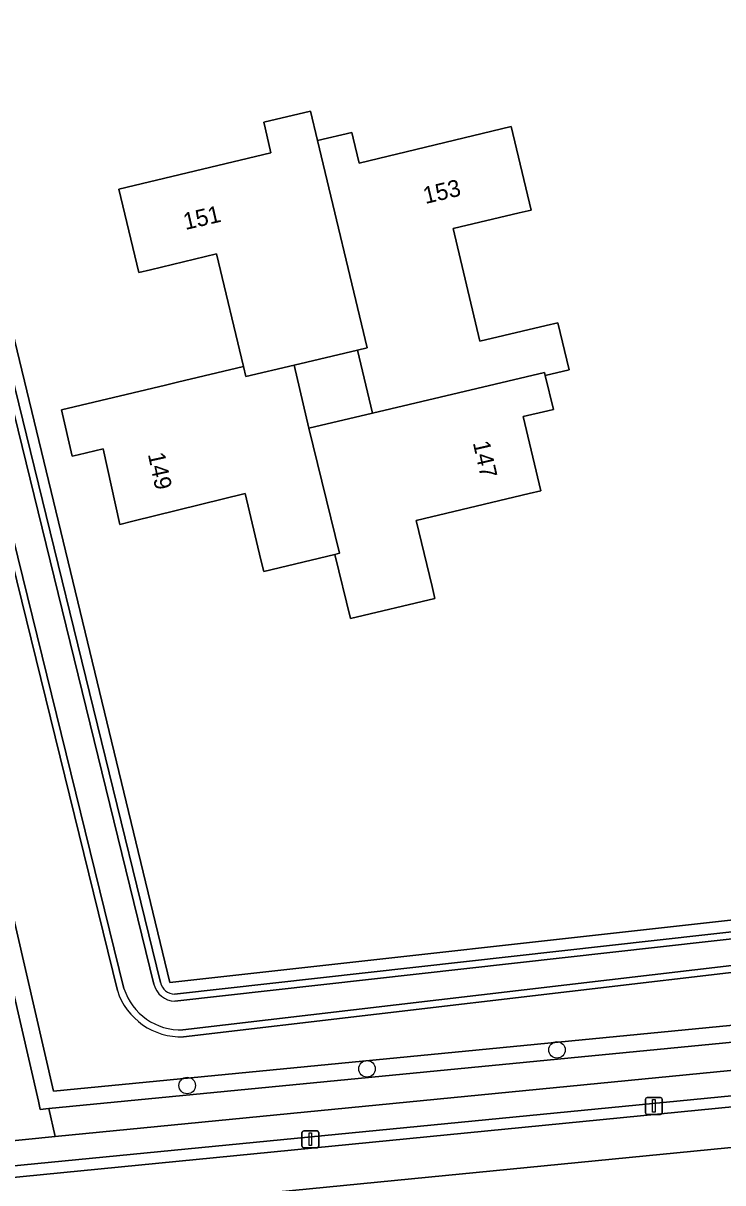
# Model space of a CAD drawing. Extents: x 156661 to 157576, y 383570 to 384425.
# Drawn here: x 156873.3 to 156914.8, y 383918.1 to 383986.9 of the extents above; entities that cross this region are included whole.
import ezdxf

# ---------------------------------------------------------------- set-up
doc = ezdxf.new("R2010")
doc.units = 0
for name, color, linetype in [('IMGEO_Berm_groen', 7, 'Continuous'), ('IMGEO_Boom', 7, 'Continuous'), ('IMGEO_Erf', 7, 'Continuous'), ('IMGEO_Groenvoorziening', 7, 'Continuous'), ('IMGEO_Haag', 7, 'Continuous'), ('IMGEO_Hek', 7, 'Continuous'), ('IMGEO_Lichtmast', 7, 'Continuous'), ('IMGEO_Oever', 7, 'Continuous'), ('IMGEO_Pand', 7, 'Continuous'), ('IMGEO_Pand_nummerreeks', 7, 'Continuous'), ('IMGEO_Parkeervlak_open', 7, 'Continuous'), ('IMGEO_Rijbaan_lokaal_open', 7, 'Continuous'), ('IMGEO_Voetpad_open', 7, 'Continuous'), ('IMGEO_Waterloop', 7, 'Continuous')]:
    doc.layers.add(name, color=color, linetype=linetype)

msp = doc.modelspace()

# ---------------------------------------------------------------- linework, layer by layer
at = {"layer": 'IMGEO_Berm_groen'}
msp.add_lwpolyline([(156853.805, 383916.581), (156939.653, 383925.02), (156939.883, 383922.625), (156942.261, 383922.858), (156942.029, 383925.893), (156868.496, 383918.711), (156853.282, 383917.324)], dxfattribs=at)
at = {"layer": 'IMGEO_Boom'}
for centre in [(156904.96, 383926.003), (156893.698, 383924.879), (156883.044, 383923.891)]:
    msp.add_circle(centre, 0.489, dxfattribs=at)
at = {"layer": 'IMGEO_Erf'}
msp.add_lwpolyline([(156971.911, 384032.865), (156863.465, 384006.689), (156882.007, 383929.988), (156953.099, 383937.896), (156953.011, 383938.269), (156952.494, 383938.147), (156951.881, 383940.49), (156952.407, 383940.603), (156956.295, 383941.53), (156956.425, 383941.002), (156956.745, 383941.083), (156956.615, 383941.611), (156956.564, 383941.597), (156954.882, 383948.869), (156959.573, 383949.776), (156961.258, 383942.72)], dxfattribs=at)
for points in [[(156904.752, 383963.959), (156904.41, 383963.885), (156902.961, 383963.546), (156904, 383959.146), (156903.304, 383958.979), (156896.605, 383957.372), (156897.554, 383953.467), (156897.725, 383952.763), (156892.723, 383951.572), (156891.794, 383955.374), (156887.581, 383954.357), (156887.415, 383955.055), (156886.481, 383958.979), (156879.819, 383957.338), (156879.053, 383957.149), (156878.061, 383961.622), (156876.583, 383961.277), (156876.237, 383961.196), (156875.591, 383963.935), (156881.763, 383965.402), (156882.477, 383965.573), (156886.373, 383966.505), (156884.791, 383973.185), (156880.877, 383972.245), (156880.173, 383972.085), (156878.991, 383977.02), (156888.003, 383979.182), (156887.664, 383980.648), (156887.586, 383980.987), (156890.346, 383981.649), (156890.766, 383979.898), (156892.794, 383980.386), (156892.877, 383980.046), (156893.235, 383978.562), (156902.252, 383980.728), (156903.427, 383975.777), (156902.718, 383975.608), (156898.809, 383974.679), (156900.384, 383968.006), (156904.318, 383968.932), (156905.001, 383969.095), (156905.672, 383966.301), (156904.267, 383965.968)], [(156894.022, 383963.749), (156893.142, 383967.479), (156889.376, 383966.59), (156890.256, 383962.861)]]:
    msp.add_lwpolyline(points, close=True, dxfattribs=at)
at = {"layer": 'IMGEO_Groenvoorziening'}
for points in [[(156971.825, 384035.574), (156971.462, 384036.848), (156855.447, 384008.779), (156857.538, 383999.895), (156875.116, 383923.557), (156954.665, 383931.279), (156953.099, 383937.896)], [(156953.099, 383937.896), (156882.007, 383929.988), (156863.465, 384006.689), (156971.911, 384032.865), (156984.848, 383993.384), (157001.305, 383943.16), (156963.71, 383939.037), (156964.423, 383936.119), (156965.671, 383936.392)], [(156862.766, 384006.287), (156881.463, 383929.99)], [(156878.907, 383929.526), (156860.158, 384005.773)], [(156882.291, 383929.295), (156950.98, 383936.984)], [(156951.446, 383934.836), (156882.827, 383926.782)]]:
    msp.add_lwpolyline(points, dxfattribs=at)
for points in [[(156954.897, 383930.297), (156954.665, 383931.279), (156875.116, 383923.557), (156857.538, 383999.895), (156855.447, 384008.779), (156854.961, 384008.661), (156854.475, 384008.544), (156856.565, 383999.666), (156874.225, 383922.969), (156874.338, 383922.477), (156874.835, 383922.525)], [(156874.835, 383922.525), (156874.338, 383922.477), (156874.225, 383922.969), (156856.565, 383999.666), (156854.475, 384008.544), (156851.846, 384007.908), (156849.631, 384007.372), (156870.13, 383920.364), (156875.218, 383920.862)], [(156875.218, 383920.862), (156955.275, 383928.7), (156954.897, 383930.297), (156874.835, 383922.525)]]:
    msp.add_lwpolyline(points, close=True, dxfattribs=at)
for centre, radius, start, end in [((156882.353, 383930.209), 0.916, 193.84782, 266.13387), ((156882.66, 383930.715), 3.937, 197.58244, 272.43352)]:
    msp.add_arc(centre, radius, start, end, dxfattribs=at)
at = {"layer": 'IMGEO_Haag'}
msp.add_lwpolyline([(156857.538, 383999.895), (156855.447, 384008.779), (156854.961, 384008.661), (156854.475, 384008.544), (156856.565, 383999.666), (156874.225, 383922.969), (156874.338, 383922.477), (156874.835, 383922.525), (156954.897, 383930.297), (156954.665, 383931.279), (156875.116, 383923.557)], close=True, dxfattribs=at)
at = {"layer": 'IMGEO_Hek'}
msp.add_lwpolyline([(156953.099, 383937.896), (156882.007, 383929.988), (156863.465, 384006.689), (156971.911, 384032.865), (156984.848, 383993.384), (157001.305, 383943.16)], dxfattribs=at)
at = {"layer": 'IMGEO_Lichtmast'}
for p, q in [((156910.205, 383922.277), (156910.205, 383923.077)), ((156910.205, 383923.077), (156910.205, 383922.277)), ((156910.305, 383923.177), (156911.095, 383923.177)), ((156911.095, 383923.177), (156910.305, 383923.177)), ((156911.195, 383923.077), (156911.195, 383922.277)), ((156911.195, 383922.277), (156911.195, 383923.077)), ((156911.095, 383922.177), (156910.305, 383922.177)), ((156910.305, 383922.177), (156911.095, 383922.177)), ((156889.848, 383920.302), (156889.848, 383921.102)), ((156889.848, 383921.102), (156889.848, 383920.302)), ((156889.948, 383921.202), (156890.738, 383921.202)), ((156890.738, 383921.202), (156889.948, 383921.202)), ((156890.838, 383921.102), (156890.838, 383920.302)), ((156890.838, 383920.302), (156890.838, 383921.102)), ((156890.738, 383920.202), (156889.948, 383920.202)), ((156889.948, 383920.202), (156890.738, 383920.202))]:
    msp.add_line(p, q, dxfattribs=at)
for points in [[(156910.625, 383923.052), (156910.775, 383923.052), (156910.775, 383922.302), (156910.625, 383922.302), (156910.625, 383923.052)], [(156890.268, 383921.077), (156890.418, 383921.077), (156890.418, 383920.327), (156890.268, 383920.327), (156890.268, 383921.077)]]:
    msp.add_lwpolyline(points, dxfattribs=at)
for centre, start, end in [((156910.305, 383923.077), 90, 180), ((156910.305, 383923.077), 90, 180), ((156911.095, 383923.077), 0, 90), ((156911.095, 383923.077), 360, 90), ((156910.305, 383922.277), 180, 270), ((156910.305, 383922.277), 180, 270), ((156911.095, 383922.277), 270, 0), ((156911.095, 383922.277), 270, 0), ((156889.948, 383921.102), 90, 180), ((156889.948, 383921.102), 90, 180), ((156890.738, 383921.102), 0, 90), ((156890.738, 383921.102), 360, 90), ((156889.948, 383920.302), 180, 270), ((156889.948, 383920.302), 180, 270), ((156890.738, 383920.302), 270, 0), ((156890.738, 383920.302), 270, 0)]:
    msp.add_arc(centre, 0.1, start, end, dxfattribs=at)
at = {"layer": 'IMGEO_Oever'}
for points in [[(156879.298, 383929.636), (156860.453, 384006.276)], [(156862.381, 384006.152), (156881.069, 383929.893)], [(156881.463, 383929.99), (156862.766, 384006.287)], [(156860.158, 384005.773), (156878.907, 383929.526)], [(156950.98, 383936.984), (156882.291, 383929.295)], [(156882.303, 383928.888), (156951.362, 383936.616)], [(156951.392, 383935.238), (156882.795, 383927.187)], [(156882.827, 383926.782), (156951.446, 383934.836)]]:
    msp.add_lwpolyline(points, dxfattribs=at)
for centre, radius, start, end in [((156882.659, 383930.714), 3.529, 197.77868, 272.21309), ((156882.353, 383930.21), 1.323, 193.85097, 267.82859), ((156882.353, 383930.209), 0.916, 193.84782, 266.13387), ((156882.66, 383930.715), 3.937, 197.58244, 272.43352)]:
    msp.add_arc(centre, radius, start, end, dxfattribs=at)
at = {"layer": 'IMGEO_Pand'}
for points in [[(156890.766, 383979.898), (156890.346, 383981.649), (156887.586, 383980.987), (156887.664, 383980.648), (156888.003, 383979.182), (156878.991, 383977.02), (156880.173, 383972.085), (156880.877, 383972.245), (156884.791, 383973.185), (156886.373, 383966.505), (156886.515, 383965.906), (156889.376, 383966.59), (156893.142, 383967.479), (156893.71, 383967.615)], [(156890.766, 383979.898), (156893.71, 383967.615), (156893.142, 383967.479), (156894.022, 383963.749), (156904.222, 383966.156), (156904.267, 383965.968), (156905.672, 383966.301), (156905.001, 383969.095), (156904.318, 383968.932), (156900.384, 383968.006), (156898.809, 383974.679), (156902.718, 383975.608), (156903.427, 383975.777), (156902.252, 383980.728), (156893.235, 383978.562), (156892.877, 383980.046), (156892.794, 383980.386)], [(156890.256, 383962.861), (156889.376, 383966.59), (156886.515, 383965.906), (156886.373, 383966.505), (156882.477, 383965.573), (156881.763, 383965.402), (156875.591, 383963.935), (156876.237, 383961.196), (156876.583, 383961.277), (156878.061, 383961.622), (156879.053, 383957.149), (156879.819, 383957.338), (156886.481, 383958.979), (156887.415, 383955.055), (156887.581, 383954.357), (156891.794, 383955.374), (156892.069, 383955.441)], [(156890.256, 383962.861), (156892.069, 383955.441), (156891.794, 383955.374), (156892.723, 383951.572), (156897.725, 383952.763), (156897.554, 383953.467), (156896.605, 383957.372), (156903.304, 383958.979), (156904, 383959.146), (156902.961, 383963.546), (156904.41, 383963.885), (156904.752, 383963.959), (156904.267, 383965.968), (156904.222, 383966.156), (156894.022, 383963.749)]]:
    msp.add_lwpolyline(points, close=True, dxfattribs=at)
at = {"layer": 'IMGEO_Parkeervlak_open'}
msp.add_lwpolyline([(156855.097, 383914.318), (156858.629, 383914.671), (156939.883, 383922.625), (156939.653, 383925.02), (156853.805, 383916.581)], dxfattribs=at)
at = {"layer": 'IMGEO_Rijbaan_lokaal_open'}
msp.add_lwpolyline([(156970.285, 383925.601), (156957.067, 383924.307), (156955.199, 383924.125), (156952.527, 383923.863), (156946.775, 383923.3), (156944.299, 383923.058), (156942.261, 383922.858), (156939.883, 383922.625), (156858.629, 383914.671), (156859.004, 383910.155), (156866.027, 383910.844), (156867.996, 383911.037), (156904.417, 383914.609), (156912.352, 383915.387), (156960.429, 383920.102)], dxfattribs=at)
at = {"layer": 'IMGEO_Voetpad_open'}
for points in [[(156955.061, 383936.102), (156957.783, 383936.781), (156956.745, 383941.083), (156956.425, 383941.002), (156956.295, 383941.53), (156952.407, 383940.603), (156953.011, 383938.269), (156953.099, 383937.896), (156954.665, 383931.279), (156954.897, 383930.297), (156955.275, 383928.7), (156875.218, 383920.862), (156870.13, 383920.364), (156867.979, 383920.714), (156860.158, 383919.98), (156854.491, 383919.448), (156853.18, 383919.265)], [(156853.282, 383917.324), (156868.496, 383918.711), (156942.029, 383925.893), (156944.032, 383926.112), (156952.092, 383926.89), (156954.952, 383927.178), (156958.753, 383927.533), (156959.604, 383929.198), (156956.799, 383928.862), (156955.061, 383936.102)]]:
    msp.add_lwpolyline(points, dxfattribs=at)
at = {"layer": 'IMGEO_Waterloop'}
for points in [[(156860.453, 384006.276), (156879.298, 383929.636)], [(156881.069, 383929.893), (156862.381, 384006.152)], [(156951.362, 383936.616), (156882.303, 383928.888)], [(156882.795, 383927.187), (156951.392, 383935.238)]]:
    msp.add_lwpolyline(points, dxfattribs=at)
for centre, radius, start, end in [((156882.659, 383930.714), 3.529, 197.77868, 272.21309), ((156882.353, 383930.21), 1.323, 193.85097, 267.82859)]:
    msp.add_arc(centre, radius, start, end, dxfattribs=at)

# ---------------------------------------------------------------- texts
at = {"layer": 'IMGEO_Pand_nummerreeks'}
for s, rotation, p in [('153', 13.29558, (156897.16, 383976.137)), ('151', 13.04777, (156882.939, 383974.597)), ('147', 282.85812, (156899.968, 383961.987)), ('149', 282.33463, (156880.709, 383961.308))]:
    msp.add_text(s, height=1, rotation=rotation, dxfattribs=at).set_placement(p)

doc.saveas('drawing.dxf')
